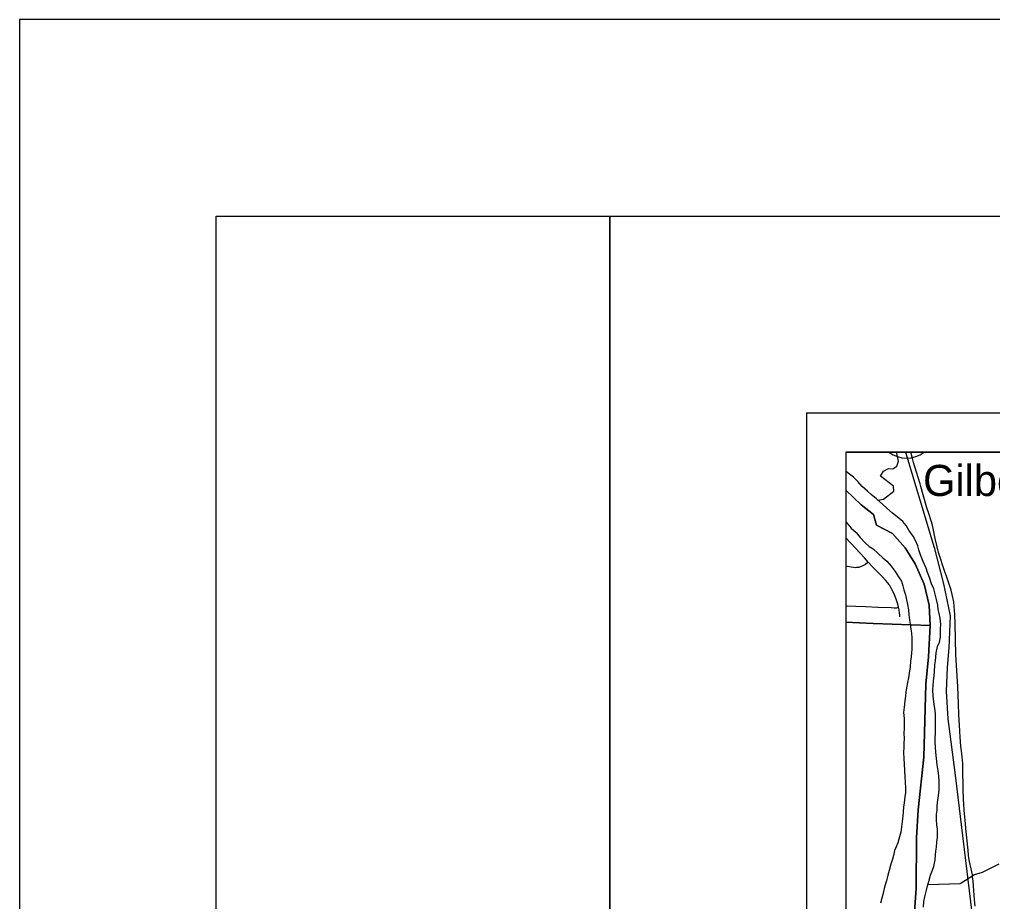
# Model space of a CAD drawing. Extents: x 0 to 34, y 0 to 22.
# Drawn here: x 0 to 2.472, y 19.758 to 22 of the extents above; entities that cross this region are included whole.
import ezdxf

# ---------------------------------------------------------------- set-up
doc = ezdxf.new("R2010")
doc.units = 0
for name, color, linetype in [('GM_X_Major_Lake', 7, 'Continuous'), ('GM_X_Major_River', 7, 'Continuous'), ('GM_X_Minor_River', 7, 'Continuous'), ('GM_X_Rail_Line', 7, 'Continuous'), ('GM_X_State_Route', 7, 'Continuous'), ('GM_X_Township_Road', 7, 'Continuous'), ('GM_X_Unincorporated_Text', 7, 'Continuous'), ('SH_Border', 7, 'Continuous'), ('SH_Cut_Line', 7, 'Continuous'), ('SH_Data', 7, 'Continuous')]:
    doc.layers.add(name, color=color, linetype=linetype)

msp = doc.modelspace()

# ---------------------------------------------------------------- linework, layer by layer
at = {"layer": 'GM_X_Major_Lake'}
msp.add_line((2.2989, 20.9), (2.2094, 20.9), dxfattribs=at)
msp.add_arc((2.2541, 20.9594), 0.0744, 233.0113, 306.9887, dxfattribs=at)
at = {"layer": 'GM_X_Major_River'}
for points in [[(2.3342, 20.5003), (2.3334, 20.5109), (2.3299, 20.5252), (2.3256, 20.5423), (2.3229, 20.5521), (2.3175, 20.5653), (2.3121, 20.5812), (2.3075, 20.5937), (2.3036, 20.6054), (2.2963, 20.6216), (2.2898, 20.639), (2.2852, 20.6518), (2.2825, 20.662), (2.2763, 20.6756), (2.2709, 20.6862), (2.2599, 20.7013), (2.253, 20.7137), (2.2446, 20.7235), (2.2305, 20.7355), (2.218, 20.7449), (2.2039, 20.7577), (2.1933, 20.7667), (2.1773, 20.781), (2.1644, 20.7926), (2.1549, 20.8005), (2.1412, 20.8125), (2.1298, 20.825), (2.1191, 20.8363), (2.1054, 20.8464), (2.1, 20.8519)], [(2.1, 20.7223), (2.1006, 20.7217), (2.1135, 20.7067), (2.1261, 20.6954), (2.1363, 20.6833), (2.1489, 20.6698), (2.1588, 20.66), (2.1687, 20.6544), (2.1816, 20.6424), (2.1938, 20.6315), (2.2041, 20.6232), (2.2151, 20.61), (2.2246, 20.5968), (2.2338, 20.5829), (2.2407, 20.5716), (2.2449, 20.5599), (2.2469, 20.55), (2.2511, 20.5376), (2.2542, 20.5247), (2.2562, 20.513), (2.2593, 20.499), (2.2598, 20.4865), (2.2614, 20.4732), (2.263, 20.4627), (2.2645, 20.4502), (2.2661, 20.4396), (2.267, 20.4282), (2.2674, 20.4127), (2.2671, 20.3994), (2.2665, 20.3896), (2.2654, 20.3793)], [(2.2968, 19.7432), (2.2982, 19.7576), (2.3004, 19.7697), (2.3044, 19.7864), (2.307, 19.7974), (2.3103, 19.8088), (2.3144, 19.8244), (2.32, 19.8373), (2.3233, 19.8468), (2.3266, 19.8639), (2.3277, 19.876), (2.3287, 19.8858), (2.3302, 19.8961), (2.3312, 19.9093), (2.3323, 19.9203), (2.3326, 19.9302), (2.3322, 19.9415), (2.3306, 19.9525), (2.3301, 19.9662), (2.3304, 19.9794), (2.3315, 19.9897), (2.3321, 19.9999), (2.3328, 20.0094), (2.3343, 20.0207), (2.3361, 20.0332), (2.3372, 20.0427), (2.3371, 20.0526), (2.3367, 20.0624), (2.3358, 20.0768), (2.3342, 20.0897), (2.3318, 20.1048), (2.3302, 20.1211), (2.3282, 20.1377), (2.3278, 20.1499), (2.3269, 20.1631), (2.3269, 20.1745), (2.3275, 20.1843), (2.3279, 20.1938), (2.3276, 20.2355), (2.326, 20.2483), (2.324, 20.2597), (2.3216, 20.2786), (2.3208, 20.2964), (2.3218, 20.307), (2.3221, 20.318), (2.3239, 20.332), (2.3246, 20.3415), (2.326, 20.3589), (2.3271, 20.3692), (2.3282, 20.379), (2.3292, 20.39), (2.3325, 20.4059), (2.3374, 20.4173), (2.3399, 20.4299), (2.3399, 20.4408), (2.3405, 20.4511), (2.3412, 20.4628), (2.3396, 20.4776), (2.3369, 20.4901), (2.3342, 20.5003)], [(2.2654, 20.3793), (2.2643, 20.3683), (2.2629, 20.3536), (2.2615, 20.3441), (2.2589, 20.3259), (2.2567, 20.3145), (2.2538, 20.3012), (2.252, 20.2902), (2.2513, 20.28), (2.2495, 20.2679), (2.2477, 20.2516), (2.2466, 20.2379), (2.2479, 20.2231), (2.248, 20.211), (2.2477, 20.1978), (2.2474, 20.1856), (2.2475, 20.1716), (2.2472, 20.1603), (2.2472, 20.15), (2.2466, 20.1364), (2.2467, 20.1209), (2.2475, 20.1069), (2.2491, 20.0906), (2.25, 20.0747), (2.2504, 20.061), (2.2509, 20.0455), (2.251, 20.0349), (2.2499, 20.0239), (2.2481, 20.0088), (2.2463, 19.9974), (2.2453, 19.9868), (2.2442, 19.975), (2.2424, 19.9614), (2.241, 19.9477), (2.2392, 19.9341), (2.2344, 19.9162), (2.2314, 19.9064), (2.2273, 19.8969), (2.2236, 19.887), (2.221, 19.8749), (2.2181, 19.8654), (2.2136, 19.8524), (2.2096, 19.8365), (2.2062, 19.8247), (2.2026, 19.8103), (2.1996, 19.8001), (2.197, 19.7906), (2.1933, 19.7758), (2.1915, 19.7663), (2.1874, 19.753)]]:
    msp.add_lwpolyline(points, dxfattribs=at)
at = {"layer": 'GM_X_Minor_River'}
for points in [[(2.1812, 20.7775), (2.1957, 20.7802), (2.2213, 20.8004), (2.2204, 20.8133), (2.1878, 20.8388), (2.1956, 20.8518), (2.2084, 20.8583), (2.2187, 20.8576), (2.2292, 20.8641), (2.2337, 20.877), (2.2287, 20.9)], [(2.3081, 19.8011), (2.3904, 19.8034), (2.427, 19.826), (2.4473, 19.8319), (2.4892, 19.8534)]]:
    msp.add_lwpolyline(points, dxfattribs=at)
at = {"layer": 'GM_X_Rail_Line'}
for points in [[(5.68, 20.9), (2.1, 20.9), (2.1, 20.8036), (2.1385, 20.7664), (2.1702, 20.7413), (2.1775, 20.7146), (2.2186, 20.6936), (2.2501, 20.6571), (2.2761, 20.6158), (2.2985, 20.5646), (2.3111, 20.5113), (2.3139, 20.4594), (2.3097, 20.3795), (2.3031, 20.3104), (2.2975, 20.1247), (2.2836, 19.9906), (2.2791, 19.9199), (2.2784, 19.7904), (2.2736, 19.7201)], [(2.2513, 20.9), (2.3238, 20.6572), (2.348, 20.5654), (2.3649, 20.4837), (2.3615, 20.4025), (2.3572, 20.3523), (2.3543, 20.2921), (2.3586, 20.2219), (2.3772, 20.0785), (2.4395, 19.568)], [(2.2736, 19.7201), (2.2784, 19.7904), (2.2791, 19.9199), (2.2836, 19.9906), (2.2975, 20.1247), (2.3031, 20.3104), (2.3097, 20.3795), (2.3139, 20.4594), (2.1695, 20.4643), (2.1, 20.4677), (2.1, 18.4819)]]:
    msp.add_lwpolyline(points, dxfattribs=at)
msp.add_lwpolyline([(2.1, 20.8036), (2.1, 20.4677), (2.1695, 20.4643), (2.3139, 20.4594), (2.3111, 20.5113), (2.2985, 20.5646), (2.2761, 20.6158), (2.2501, 20.6571), (2.2186, 20.6936), (2.1775, 20.7146), (2.1702, 20.7413), (2.1385, 20.7664)], close=True, dxfattribs=at)
at = {"layer": 'GM_X_State_Route'}
for points in [[(2.3905, 20.175), (2.3881, 20.206), (2.3868, 20.2322), (2.3863, 20.261), (2.3839, 20.3032), (2.379, 20.3858), (2.3777, 20.4625), (2.377, 20.4871), (2.3752, 20.5076), (2.3738, 20.5195), (2.3698, 20.5377), (2.3671, 20.5495), (2.3632, 20.5619), (2.3553, 20.5843), (2.3509, 20.5959), (2.346, 20.6106), (2.34, 20.6299), (2.3353, 20.6452), (2.3316, 20.6595), (2.3267, 20.6805), (2.3195, 20.7145), (2.3166, 20.7254), (2.3104, 20.7441), (2.3055, 20.7582), (2.3034, 20.7644), (2.2902, 20.8129), (2.2884, 20.8198), (2.2835, 20.8356), (2.2717, 20.8736), (2.269, 20.8838), (2.2652, 20.9)], [(2.4218, 19.8216), (2.4214, 19.8255), (2.4182, 19.841), (2.414, 19.8595), (2.4122, 19.8689), (2.4113, 19.8758), (2.4103, 19.8881), (2.4049, 19.9432), (2.4034, 19.956), (2.4007, 19.9888), (2.3994, 20.006), (2.3987, 20.0169), (2.3979, 20.0433), (2.3972, 20.0968), (2.3967, 20.1089), (2.3952, 20.1253), (2.3936, 20.1406), (2.3922, 20.1529), (2.3905, 20.175)], [(2.423, 19.8099), (2.4226, 19.8147), (2.4218, 19.8216)], [(2.4283, 19.7461), (2.4265, 19.7621), (2.4241, 19.7974), (2.423, 19.8099)]]:
    msp.add_lwpolyline(points, dxfattribs=at)
at = {"layer": 'GM_X_Township_Road'}
for points in [[(2.1566, 20.6205), (2.1474, 20.631), (2.1241, 20.656), (2.1, 20.6819)], [(2.1, 20.6109), (2.1037, 20.61), (2.1128, 20.6082), (2.1189, 20.6074), (2.125, 20.6071), (2.1279, 20.6072), (2.1309, 20.6075), (2.1338, 20.608), (2.1396, 20.6098), (2.1424, 20.611), (2.1451, 20.6124), (2.1503, 20.6156), (2.1525, 20.6174), (2.1566, 20.6205)], [(2.2333, 20.5058), (2.2324, 20.51), (2.2309, 20.5164), (2.2286, 20.5236), (2.2252, 20.5327), (2.2213, 20.5418), (2.2161, 20.5525), (2.2112, 20.5608), (2.2061, 20.5677), (2.2002, 20.5749), (2.1919, 20.584), (2.166, 20.6104), (2.1575, 20.6194), (2.1566, 20.6205)], [(2.1, 20.5093), (2.1033, 20.5092), (2.125, 20.5082), (2.1497, 20.5072), (2.1807, 20.5063), (2.2147, 20.5047), (2.2225, 20.5042), (2.2261, 20.5043), (2.2292, 20.5046), (2.2323, 20.5055), (2.2333, 20.5058)], [(2.2373, 20.4812), (2.2369, 20.486), (2.2362, 20.4907), (2.2348, 20.4988), (2.2333, 20.5058)]]:
    msp.add_lwpolyline(points, dxfattribs=at)
at = {"layer": 'SH_Border'}
for points in [[(0.5, 21.5), (1.5, 21.5), (1.5, 0.5), (0.5, 0.5)], [(1.5, 21.5), (33.5, 21.5), (33.5, 0.5), (1.5, 0.5)]]:
    msp.add_lwpolyline(points, close=True, dxfattribs=at)
at = {"layer": 'SH_Cut_Line'}
msp.add_lwpolyline([(0, 0), (34, 0), (34, 22), (0, 22)], close=True, dxfattribs=at)
at = {"layer": 'SH_Data'}
for p, q in [((2, 21), (9, 21)), ((2, 21), (2, 14)), ((2.1, 20.9), (2.1, 14.1)), ((2.1, 20.9), (8.9, 20.9))]:
    msp.add_line(p, q, dxfattribs=at)

# ---------------------------------------------------------------- texts
at = {"layer": 'GM_X_Unincorporated_Text'}
msp.add_text('Gilbert', height=0.07898, rotation=0, dxfattribs=at).set_placement((2.2959, 20.7886))

doc.saveas('drawing.dxf')
